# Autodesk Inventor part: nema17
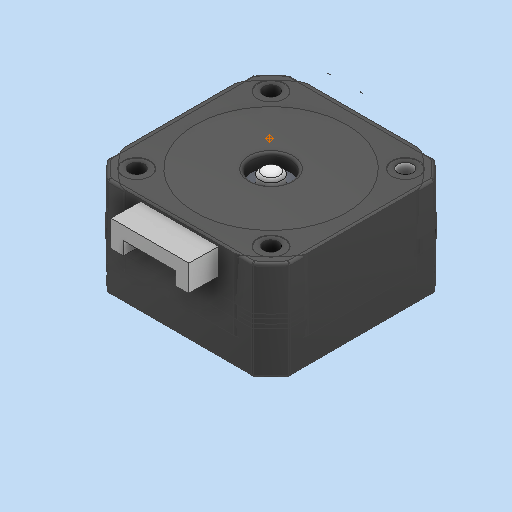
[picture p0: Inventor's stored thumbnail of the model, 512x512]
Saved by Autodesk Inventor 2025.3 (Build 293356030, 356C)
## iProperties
Created: 2022-12
Part Number: nema17
Material: Titanio
Document SubType Name: Modeling
Designer: Ryzen5700u
Density: 4.51 g/cm^3
Appearance: Titanio
Author: Ryzen5700u
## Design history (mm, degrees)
body "Solid1"
body "Solid2"
body "Solid3"
node "Punto di riferimento1"
sketch "Schizzo1"
  geometry: L1 (-2.267, 2)-(2.725, 2); C1 r 2.5 at (0, 0) reference; 3 further points
  constraints: 2 end point, 1 horizontal
  dimensions: "d0" = 2 distance from line of point (0, 0) L1
extrude "Estrusione1" cut sketch "Schizzo1" distance "d1" = 20; taper "d2" = 0 deg
chamfer "Smusso1" distance "d3" = 0.5; stored, may be unused: second distance "d4" = 2, angle "d5" = 45 deg
sketch "Schizzo2"
  geometry: L1 (8, -4)-(7.479, -4) reference; L2 (8, -4)-(8, 0) reference; L3 (8, 0)-(0, 0) reference; L4 (0, -4)-(0, 0) reference; L5 (0.521, -4)-(0, -4) reference; L6 (9.468, 2.619)-(0, 2.619); L7 (0, 2.619)-(0, -7.291); L8 (0, -7.291)-(9.468, -7.291); L9 (9.468, -7.291)-(9.468, 2.619); A1 r 17.497 centre (4, -21.148) between (7.479, -4) and (0.521, -4) reference; 3 further points
  constraints: 8 end point, 2 parallel, 1 horizontal, 1 perpendicular
extrude "Estrusione2" cut sketch "Schizzo2" stored distance "d6" = 10; taper "d7" = 0 deg
sketch "Schizzo3"
  geometry: L1 (25.515, 0.059)-(7.515, 0.059); L2 (7.515, 0.059)-(7.515, -9.941); L3 (7.515, -9.941)-(25.515, -9.941); L4 (25.515, -9.941)-(25.515, 0.059); L5 (33.029, -27.872)-(0, -27.872) reference; L6 (16.515, -27.872)-(16.515, 5.454); 1 further point
  constraints: 10 end point, 2 parallel, 1 horizontal, 1 midpoint, 1 perpendicular, 1 vertical, 1 other
  dimensions: "d8" = 18 distance of L3.end L2.end; "d9" = 10 distance of L2.end L1.end
extrude "Estrusione3" join sketch "Schizzo3" distance "d10" = 7; taper "d11" = 0 deg
node "Modifica diretta1"
node "Modifica diretta2"
sketch "Schizzo4"
  geometry: L1 (15, 12)-(3, 12); L2 (3, 12)-(3, 2); L3 (3, 2)-(15, 2); L4 (15, 2)-(15, 12); L5 (18, 7)-(0, 7) reference; L6 (15, 12)-(3, 2); L7 (3, 12)-(15, 2); 4 further points
  constraints: 12 end point, 3 midpoint, 2 parallel, 1 horizontal, 1 perpendicular
extrude "Estrusione4" cut sketch "Schizzo4" distance "d24" = 7; taper "d25" = 0 deg
sketch "Schizzo5"
  geometry: L1 (15, -10)-(18, -10) reference; L2 (18, -10)-(0, -10); L3 (0, -10)-(0, -6); L4 (0, -6)-(18, -6); L5 (18, -6)-(18, -10); 2 further points
  constraints: 8 end point, 2 parallel, 1 horizontal, 1 perpendicular
extrude "Estrusione5" cut sketch "Schizzo5" stored distance "d26" = 7; taper "d27" = 0 deg
node "Solido1"
node "Solido2"
node "Solido3"
node "Linea chiusa proiettata1"
feature "Sposta1" dims "d20" = 6.79
feature "Sposta2" dims "d23" = 2.5
other parameters: "d18" = 0, "d19" = 0, "d21" = 0, "d22" = 0
